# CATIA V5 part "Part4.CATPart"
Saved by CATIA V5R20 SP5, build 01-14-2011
Part number: Part4
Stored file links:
  D:\zhonggao\Part4.CATPart
  D:\半稿\Part2.CATPart
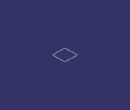
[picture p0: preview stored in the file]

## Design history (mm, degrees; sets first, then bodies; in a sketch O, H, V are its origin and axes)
Body1 (main body)
  DatumSurface1 to DatumSurface3
  Sketch1 on face of DatumSurface3, origin (0, -12.5, 0), H (-1, 0, 0), V (0, 0, 1)
    polyline C1
    polyline C2
    polyline C3
    polyline C4
    polyline C5
    polyline C6
    polyline C7
    polyline C8
    polyline C9
    polyline C10
    polyline C11
    polyline C12
    polyline C13
    polyline C14
    polyline C15
    polyline C16
    polyline C17
    polyline C18
    polyline C19
    polyline C20
    polyline C21
    polyline C22
    polyline C23
    polyline C24
    polyline C25
  Pad1: profile Sketch1, direction (0, 1, 0), length 8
